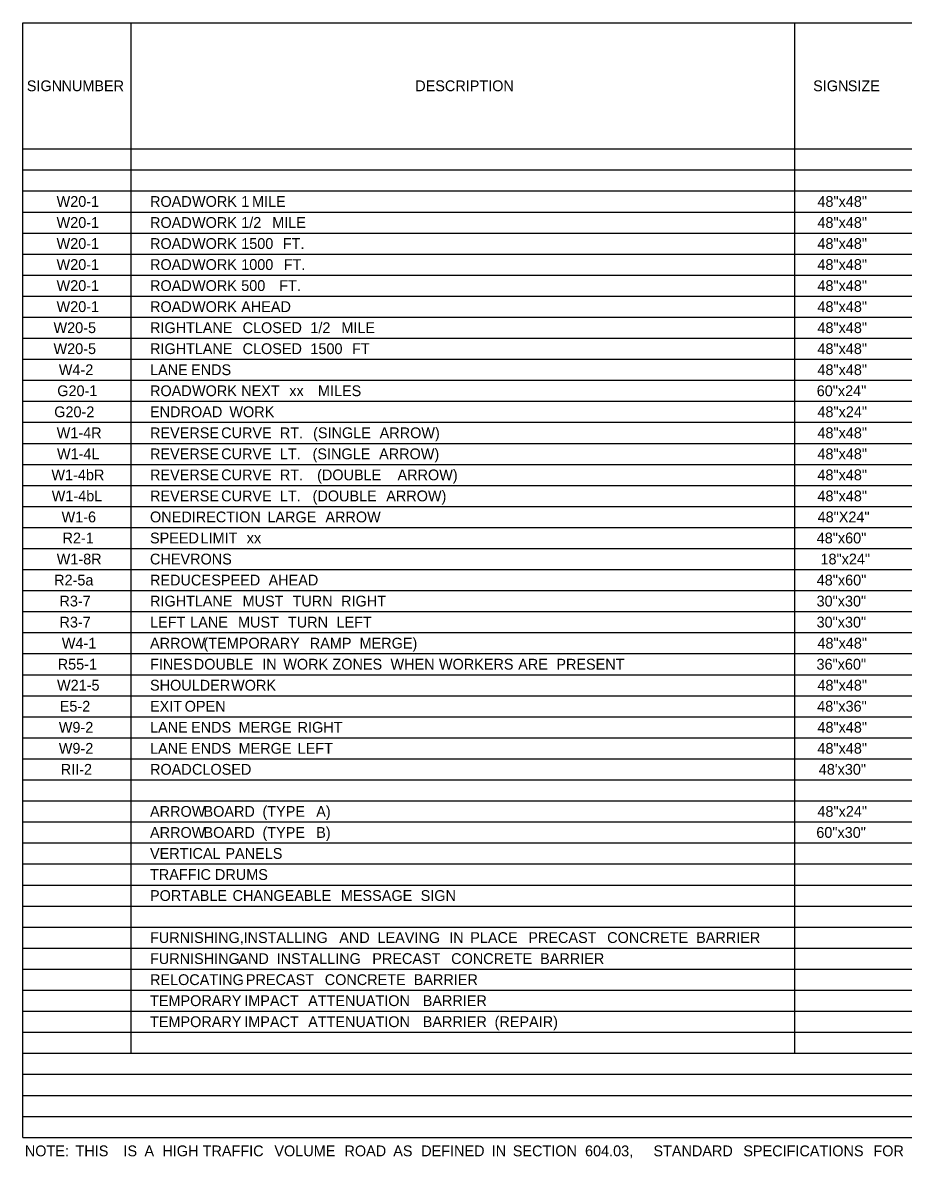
# Model space of a CAD drawing. Extents: x 1225909 to 1228704, y 151309 to 152305.
# Drawn here: x 1226577.4 to 1226842.6, y 151937.4 to 152279.6 of the extents above; entities that cross this region are included whole.
import ezdxf

# ---------------------------------------------------------------- set-up
doc = ezdxf.new("R2010")
doc.units = 0
doc.layers.add('R_Dimension', color=7, linetype='Continuous')

msp = doc.modelspace()

# ---------------------------------------------------------------- linework, layer by layer
at = {"layer": 'R_Dimension'}
for p, q in [((1226577.42, 152279.62), (1227591.1, 152279.62)), ((1226577.42, 151943.73), (1226577.42, 152279.62)), ((1226610.06, 151969.08), (1226610.06, 152279.62)), ((1226810.01, 151969.08), (1226810.01, 152279.62)), ((1226577.42, 152241.6), (1227591.1, 152241.6)), ((1226577.42, 152235.26), (1227591.1, 152235.26)), ((1226577.42, 152228.92), (1227591.1, 152228.92)), ((1226577.42, 152222.58), (1227591.1, 152222.58)), ((1226577.42, 152216.25), (1227591.1, 152216.25)), ((1226577.42, 152209.91), (1227591.1, 152209.91)), ((1226577.42, 152203.57), (1227591.1, 152203.57)), ((1226577.42, 152197.23), (1227591.1, 152197.23)), ((1226577.42, 152190.9), (1227591.1, 152190.9)), ((1226577.42, 152184.56), (1227591.1, 152184.56)), ((1226577.42, 152178.22), (1227591.1, 152178.22)), ((1226577.42, 152171.88), (1227591.1, 152171.88)), ((1226577.42, 152165.55), (1227591.1, 152165.55)), ((1226577.42, 152159.21), (1227591.1, 152159.21)), ((1226577.42, 152152.87), (1227591.1, 152152.87)), ((1226577.42, 152146.53), (1227591.1, 152146.53)), ((1226577.42, 152140.2), (1227591.1, 152140.2)), ((1226577.42, 152133.86), (1227591.1, 152133.86)), ((1226577.42, 152127.52), (1227591.1, 152127.52)), ((1226577.42, 152121.18), (1227591.1, 152121.18)), ((1226577.42, 152114.85), (1227591.1, 152114.85)), ((1226577.42, 152108.51), (1227591.1, 152108.51)), ((1226577.42, 152102.17), (1227591.1, 152102.17)), ((1226577.42, 152095.83), (1227591.1, 152095.83)), ((1226577.42, 152089.5), (1227591.1, 152089.5)), ((1226577.42, 152083.16), (1227591.1, 152083.16)), ((1226577.42, 152076.82), (1227591.1, 152076.82)), ((1226577.42, 152070.48), (1227591.1, 152070.48)), ((1226577.42, 152064.15), (1227591.1, 152064.15)), ((1226577.42, 152057.81), (1227591.1, 152057.81)), ((1226577.42, 152051.47), (1227591.1, 152051.47)), ((1226577.42, 152045.13), (1227591.1, 152045.13)), ((1226577.42, 152038.8), (1227591.1, 152038.8)), ((1226577.42, 152032.46), (1227591.1, 152032.46)), ((1226577.42, 152026.12), (1227591.1, 152026.12)), ((1226577.42, 152019.78), (1227591.1, 152019.78)), ((1226577.42, 152013.45), (1227591.1, 152013.45)), ((1226577.42, 152007.11), (1227591.1, 152007.11)), ((1226577.42, 152000.77), (1227591.1, 152000.77)), ((1226577.42, 151994.43), (1227591.1, 151994.43)), ((1226577.42, 151988.1), (1227591.1, 151988.1)), ((1226577.42, 151981.76), (1227591.1, 151981.76)), ((1226577.42, 151975.42), (1227591.1, 151975.42)), ((1226577.42, 151969.08), (1227591.1, 151969.08)), ((1226577.42, 151962.75), (1227591.1, 151962.75)), ((1226577.42, 151956.41), (1227591.1, 151956.41)), ((1226577.42, 151950.07), (1227591.1, 151950.07)), ((1226577.42, 151943.73), (1227591.1, 151943.73))]:
    msp.add_line(p, q, dxfattribs=at)

# ---------------------------------------------------------------- texts
for s, p in [('SIGN', (1226578.65, 152258.98)), (' NUMBER', (1226587.89, 152258.98)), ('DESCRIPTION', (1226695.64, 152258.98)), ('SIGN', (1226815.48, 152258.98)), (' SIZE', (1226824.71, 152258.98)), ('W20-1', (1226587.62, 152224.13)), ('ROAD', (1226615.76, 152224.13)), (' WORK', (1226627.2, 152224.13)), (' 1', (1226642.02, 152224.13)), (' MILE', (1226645.27, 152224.13)), ('48"x48"', (1226816.77, 152224.13)), ('W20-1', (1226587.62, 152217.79)), ('ROAD', (1226615.76, 152217.79)), (' WORK', (1226627.2, 152217.79)), (' 1/2', (1226642.02, 152217.79)), (' MILE', (1226651.36, 152217.79)), ('48"x48"', (1226816.77, 152217.79)), ('W20-1', (1226587.62, 152211.45)), ('ROAD', (1226615.76, 152211.45)), (' WORK', (1226627.2, 152211.45)), (' 1500', (1226642.02, 152211.45)), (' FT.', (1226654.56, 152211.45)), ('48"x48"', (1226816.77, 152211.45)), ('W20-1', (1226587.62, 152205.12)), ('ROAD', (1226615.76, 152205.12)), (' WORK', (1226627.2, 152205.12)), (' 1000', (1226642.02, 152205.12)), (' FT.', (1226654.81, 152205.12)), ('48"x48"', (1226816.77, 152205.12)), ('W20-1', (1226587.62, 152198.78)), ('ROAD', (1226615.76, 152198.78)), (' WORK', (1226627.2, 152198.78)), (' 500', (1226642.02, 152198.78)), (' FT.', (1226653.48, 152198.78)), ('48"x48"', (1226816.77, 152198.78)), ('W20-1', (1226587.62, 152192.44)), ('ROAD', (1226615.76, 152192.44)), (' WORK', (1226627.2, 152192.44)), (' AHEAD', (1226642.02, 152192.44)), ('48"x48"', (1226816.77, 152192.44)), ('W20-5', (1226586.7, 152186.1)), ('RIGHT', (1226615.76, 152186.1)), (' LANE', (1226628.02, 152186.1)), (' CLOSED', (1226642.43, 152186.1)), (' 1/2', (1226662.85, 152186.1)), (' MILE', (1226672.19, 152186.1)), ('48"x48"', (1226816.77, 152186.1)), ('W20-5', (1226586.7, 152179.77)), ('RIGHT', (1226615.76, 152179.77)), (' LANE', (1226628.02, 152179.77)), (' CLOSED', (1226642.43, 152179.77)), (' 1500', (1226662.85, 152179.77)), (' FT', (1226675.39, 152179.77)), ('48"x48"', (1226816.77, 152179.77)), ('W4-2', (1226588.29, 152173.43)), ('LANE', (1226615.76, 152173.43)), (' ENDS', (1226626.92, 152173.43)), ('48"x48"', (1226816.77, 152173.43)), ('G20-1', (1226587.83, 152167.09)), ('ROAD', (1226615.76, 152167.09)), (' WORK', (1226627.2, 152167.09)), (' NEXT', (1226642.02, 152167.09)), (' xx', (1226656.5, 152167.09)), (' MILES', (1226665.13, 152167.09)), ('60"x24"', (1226816.56, 152167.09)), ('G20-2', (1226586.91, 152160.75)), ('END', (1226615.76, 152160.75)), (' ROAD', (1226623.77, 152160.75)), (' WORK', (1226638.46, 152160.75)), ('48"x24"', (1226816.77, 152160.75)), ('W1-4R', (1226587.66, 152154.42)), ('REVERSE', (1226615.76, 152154.42)), (' CURVE', (1226635.98, 152154.42)), (' RT.', (1226653.66, 152154.42)), (' (SINGLE', (1226663.67, 152154.42)), (' ARROW)', (1226683.71, 152154.42)), ('48"x48"', (1226816.77, 152154.42)), ('W1-4L', (1226587.75, 152148.08)), ('REVERSE', (1226615.76, 152148.08)), (' CURVE', (1226635.98, 152148.08)), (' LT.', (1226653.66, 152148.08)), (' (SINGLE', (1226663.51, 152148.08)), (' ARROW)', (1226683.55, 152148.08)), ('48"x48"', (1226816.77, 152148.08)), ('W1-4bR', (1226586.07, 152141.74)), ('REVERSE', (1226615.76, 152141.74)), (' CURVE', (1226635.98, 152141.74)), (' RT.', (1226653.66, 152141.74)), ('  (DOUBLE', (1226663.67, 152141.74)), (' ARROW)', (1226689.1, 152141.74)), ('48"x48"', (1226816.77, 152141.74)), ('W1-4bL', (1226586.16, 152135.4)), ('REVERSE', (1226615.76, 152135.4)), (' CURVE', (1226635.98, 152135.4)), (' LT.', (1226653.66, 152135.4)), (' (DOUBLE', (1226663.51, 152135.4)), (' ARROW)', (1226685.7, 152135.4)), ('48"x48"', (1226816.77, 152135.4)), ('W1-6', (1226589.12, 152129.07)), ('ONE', (1226615.76, 152129.07)), (' DIRECTION', (1226624, 152129.07)), (' LARGE', (1226649.9, 152129.07)), (' ARROW', (1226667.38, 152129.07)), ('48"X24"', (1226816.82, 152129.07)), ('R2-1', (1226589.41, 152122.73)), ('SPEED', (1226615.76, 152122.73)), (' LIMIT', (1226629.76, 152122.73)), (' xx', (1226643.68, 152122.73)), ('48"x60"', (1226816.56, 152122.73)), ('W1-8R', (1226587.66, 152116.39)), ('CHEVRONS', (1226615.76, 152116.39)), ('18"x24"', (1226817.69, 152116.39)), ('R2-5a', (1226586.88, 152110.05)), ('REDUCE', (1226615.76, 152110.05)), (' SPEED', (1226633.01, 152110.05)), (' AHEAD', (1226650.26, 152110.05)), ('48"x60"', (1226816.56, 152110.05)), ('R3-7', (1226588.49, 152103.72)), ('RIGHT', (1226615.76, 152103.72)), (' LANE', (1226628.02, 152103.72)), (' MUST', (1226642.43, 152103.72)), (' TURN', (1226657.47, 152103.72)), (' RIGHT', (1226672.11, 152103.72)), ('30"x30"', (1226816.51, 152103.72)), ('R3-7', (1226588.49, 152097.38)), ('LEFT', (1226615.76, 152097.38)), (' LANE', (1226626.64, 152097.38)), (' MUST', (1226641.05, 152097.38)), (' TURN', (1226656.09, 152097.38)), (' LEFT', (1226670.73, 152097.38)), ('30"x30"', (1226816.51, 152097.38)), ('W4-1', (1226589.21, 152091.04)), ('ARROW', (1226615.76, 152091.04)), (' (TEMPORARY', (1226630.66, 152091.04)), (' RAMP', (1226662.67, 152091.04)), (' MERGE)', (1226677.67, 152091.04)), ('48"x48"', (1226816.77, 152091.04)), ('R55-1', (1226587.96, 152084.7)), ('FINES', (1226615.76, 152084.7)), (' DOUBLE', (1226627.74, 152084.7)), (' IN', (1226648.34, 152084.7)), (' WORK', (1226654.69, 152084.7)), (' ZONES', (1226669.5, 152084.7)), (' WHEN', (1226686.98, 152084.7)), (' WORKERS', (1226701.57, 152084.7)), (' ARE', (1226725.44, 152084.7)), (' PRESENT', (1226736.93, 152084.7)), ('36"x60"', (1226816.49, 152084.7)), ('W21-5', (1226587.75, 152078.37)), ('SHOULDER', (1226615.76, 152078.37)), (' WORK', (1226638.97, 152078.37)), ('48"x48"', (1226816.77, 152078.37)), ('E5-2', (1226588.57, 152072.03)), ('EXIT', (1226615.76, 152072.03)), (' OPEN', (1226625, 152072.03)), ('48"x36"', (1226816.69, 152072.03)), ('W9-2', (1226588.29, 152065.69)), ('LANE', (1226615.76, 152065.69)), (' ENDS', (1226626.92, 152065.69)), (' MERGE', (1226641.22, 152065.69)), (' RIGHT', (1226659.01, 152065.69)), ('48"x48"', (1226816.77, 152065.69)), ('W9-2', (1226588.29, 152059.35)), ('LANE', (1226615.76, 152059.35)), (' ENDS', (1226626.92, 152059.35)), (' MERGE', (1226641.22, 152059.35)), (' LEFT', (1226659.01, 152059.35)), ('48"x48"', (1226816.77, 152059.35)), ('RII-2', (1226588.88, 152053.02)), ('ROAD', (1226615.76, 152053.02)), (' CLOSED', (1226627.2, 152053.02)), ('48\'x30"', (1226817.18, 152053.02)), ('ARROW', (1226615.76, 152040.34)), (' BOARD', (1226630.66, 152040.34)), (' (TYPE', (1226648.42, 152040.34)), (' A)', (1226664.61, 152040.34)), ('48"x24"', (1226816.77, 152040.34)), ('ARROW', (1226615.76, 152034)), (' BOARD', (1226630.66, 152034)), (' (TYPE', (1226648.42, 152034)), (' B)', (1226664.61, 152034)), ('60"x30"', (1226816.43, 152034)), ('VERTICAL', (1226615.76, 152027.67)), (' PANELS', (1226637.26, 152027.67)), ('TRAFFIC', (1226615.76, 152021.33)), (' DRUMS', (1226634.11, 152021.33)), ('PORTABLE', (1226615.76, 152014.99)), (' CHANGEABLE', (1226639.41, 152014.99)), (' MESSAGE', (1226672.04, 152014.99)), (' SIGN', (1226696.07, 152014.99)), ('FURNISHING,', (1226615.76, 152002.32)), (' INSTALLING', (1226642.73, 152002.32)), (' AND', (1226671.55, 152002.32)), (' LEAVING', (1226683.07, 152002.32)), (' IN', (1226704.66, 152002.32)), (' PLACE', (1226711.01, 152002.32)), (' PRECAST', (1226728.49, 152002.32)), (' CONCRETE', (1226752.24, 152002.32)), (' BARRIER', (1226779.03, 152002.32)), ('FURNISHING', (1226615.76, 151995.98)), (' AND', (1226641.17, 151995.98)), (' INSTALLING', (1226652.69, 151995.98)), (' PRECAST', (1226681.5, 151995.98)), (' CONCRETE', (1226705.25, 151995.98)), (' BARRIER', (1226732.05, 151995.98)), ('RELOCATING', (1226615.76, 151989.64)), (' PRECAST', (1226643.43, 151989.64)), (' CONCRETE', (1226667.17, 151989.64)), (' BARRIER', (1226693.97, 151989.64)), ('TEMPORARY', (1226615.76, 151983.3)), (' IMPACT', (1226642.94, 151983.3)), (' ATTENUATION', (1226662.18, 151983.3)), (' BARRIER', (1226696.68, 151983.3)), ('TEMPORARY', (1226615.76, 151976.97)), (' IMPACT', (1226642.94, 151976.97)), (' ATTENUATION', (1226662.18, 151976.97)), (' BARRIER', (1226696.68, 151976.97)), (' (REPAIR)', (1226718.33, 151976.97)), ('NOTE:', (1226578.05, 151938.05)), ('  THIS', (1226590.9, 151938.05)), (' IS', (1226606.56, 151938.05)), (' HIGH', (1226618.26, 151938.05)), (' TRAFFIC', (1226630.41, 151938.05)), (' VOLUME', (1226652.01, 151938.05)), (' ROAD', (1226673.12, 151938.05)), (' AS', (1226687.81, 151938.05)), (' SECTION', (1226723.82, 151938.05)), (' 604.03,', (1226745.57, 151938.05)), (' STANDARD', (1226766.17, 151938.05)), (' SPECIFICATIONS', (1226793.24, 151938.05)), (' FOR', (1226832.42, 151938.05)), (' A', (1226612.88, 151938.05)), (' DEFINED', (1226696.23, 151938.05)), (' IN', (1226717.47, 151938.05))]:
    msp.add_text(s, height=3.25, dxfattribs=at).set_placement(p)

doc.saveas('drawing.dxf')
